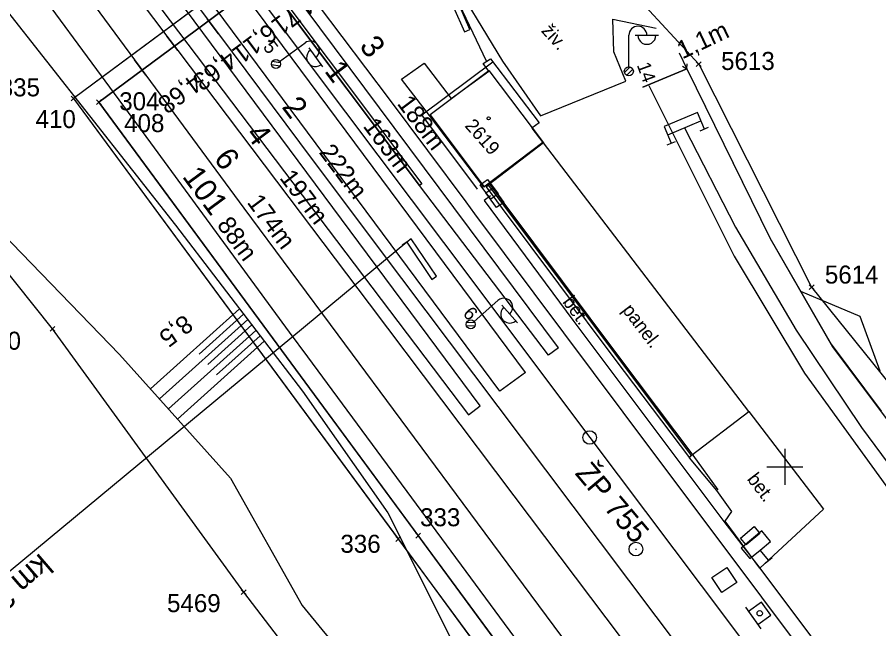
# Model space of a CAD drawing. Extents: x -804166 to -803706, y -1151030 to -1150147.
# Drawn here: x -804085.1 to -803989.6, y -1150318 to -1150250.1 of the extents above; entities that cross this region are included whole.
import ezdxf

# ---------------------------------------------------------------- set-up
doc = ezdxf.new("R2010")
doc.units = 0
for name, color, linetype in [('0381KM032-037P - Vrstva 1', 7, 'Continuous'), ('0381KM032-037P - Vrstva 12', 7, 'Continuous'), ('0381KM032-037P - Vrstva 13', 7, 'Continuous'), ('0381KM032-037P - Vrstva 14', 7, 'Continuous'), ('0381KM032-037P - Vrstva 15', 7, 'Continuous'), ('0381KM032-037P - Vrstva 16', 7, 'Continuous'), ('0381KM032-037P - Vrstva 17', 7, 'Continuous'), ('0381KM032-037P - Vrstva 23', 7, 'Continuous'), ('0381KM032-037P - Vrstva 25', 7, 'Continuous'), ('0381KM032-037P - Vrstva 3', 7, 'Continuous'), ('0381KM032-037P - Vrstva 33', 7, 'Continuous'), ('0381KM032-037P - Vrstva 4', 7, 'Continuous'), ('0381KM032-037P - Vrstva 41', 7, 'Continuous'), ('0381KM032-037P - Vrstva 48', 7, 'Continuous'), ('0381KM032-037P - Vrstva 49', 7, 'Continuous'), ('0381KM032-037P - Vrstva 51', 7, 'Continuous'), ('0381KM032-037P - Vrstva 55', 7, 'Continuous'), ('0381KM032-037P - Vrstva 57', 7, 'Continuous'), ('0381KM032-037P - Vrstva 59', 7, 'Continuous'), ('0381KM032-037P - Vrstva 7', 7, 'Continuous'), ('0381KM032-037P - Vrstva 9', 7, 'Continuous'), ('DZ_CD - CD', 7, 'Continuous'), ('DZ_CD - CD_krizek', 7, 'Continuous'), ('DZ_CD - CD_čísla', 7, 'Continuous'), ('krizky_1000 - Vrstva 1', 7, 'Continuous'), ('szdc - hran DP', 7, 'Continuous'), ('szdc - szdc_cislo', 7, 'Continuous'), ('szdc - szdc_krizek', 7, 'Continuous'), ('VB - VB', 7, 'Continuous'), ('VB - VB_cislo', 7, 'Continuous'), ('VB - VB_krizek', 7, 'Continuous'), ('vyt_sit - stávající', 7, 'Continuous')]:
    doc.layers.add(name, color=color, linetype=linetype)

msp = doc.modelspace()

# ---------------------------------------------------------------- linework, layer by layer
at = {"layer": '0381KM032-037P - Vrstva 1'}
for points in [[(-804087.926, -1150205.285), (-804078.707, -1150215.283), (-804072.371, -1150222.524), (-804072.077, -1150222.855), (-804071.467, -1150223.584), (-804065.479, -1150230.817), (-804059.467, -1150238.509), (-804055.553, -1150243.678), (-804054.356, -1150245.269), (-804043.889, -1150259.222), (-804035.374, -1150270.613), (-804034.4, -1150271.93), (-804017.97, -1150293.92), (-804002.6, -1150314.46), (-803985.38, -1150337.43), (-803955.87, -1150376.72)], [(-804089.349, -1150206.442), (-804078.67, -1150220.695), (-804069.154, -1150233.375), (-804067.857, -1150235.106), (-804059.282, -1150246.533), (-804058.068, -1150248.156), (-804048.703, -1150260.645), (-804037.85, -1150275.13), (-804021.63, -1150296.76), (-804006.14, -1150317.336), (-803988.978, -1150340.287), (-803981.901, -1150349.725)], [(-804090.387, -1150214.375), (-804086.648, -1150219.546), (-804073.823, -1150237.114), (-804072.555, -1150238.826), (-804064.047, -1150250.31), (-804062.807, -1150251.974), (-804052.288, -1150266.049), (-804042.5, -1150279.11), (-804026.546, -1150300.334), (-804011.272, -1150320.629), (-803993.373, -1150344.487), (-803965.171, -1150382.072), (-803953.841, -1150397.189)], [(-804093.97, -1150217.423), (-804088.165, -1150225.674), (-804077.507, -1150240.279), (-804068.519, -1150252.214), (-804067.312, -1150253.815), (-804055.014, -1150270.122), (-804046.09, -1150281.931), (-804030.046, -1150303.209), (-804014.756, -1150323.518), (-803996.92, -1150347.354), (-803968.884, -1150385.416), (-803942.597, -1150419.033)], [(-804095.554, -1150218.377), (-804090.738, -1150227.081), (-804084.011, -1150238.21), (-804078.761, -1150245.777), (-804072.115, -1150254.848), (-804070.853, -1150256.555), (-804059.975, -1150271.287), (-804049.56, -1150285.37), (-804034.127, -1150306.216), (-804018.794, -1150326.862), (-804001.176, -1150350.631), (-803980.37, -1150378.683), (-803972.82, -1150388.417), (-803965.206, -1150397.597)], [(-804088.45, -1150239.448), (-804070.362, -1150264.071), (-804054.977, -1150285.047), (-804052.95, -1150287.79), (-804037.556, -1150308.636), (-804021.871, -1150329.906), (-804004.483, -1150353.558), (-803990.764, -1150372.094)], [(-804011.14, -1150262.39), (-804005.45, -1150273.41), (-803998.73, -1150284.85), (-803991.51, -1150295.63), (-803978.8, -1150312.77), (-803963.69, -1150332.99), (-803952.21, -1150348.36), (-803946.3, -1150356.39), (-803941.6, -1150363.14), (-803936.71, -1150370.83), (-803932.05, -1150378.84), (-803927.78, -1150386.91), (-803924.06, -1150395.18), (-803920.62, -1150403.65), (-803918.06, -1150410.86), (-803915.07, -1150420.32), (-803912.96, -1150427.25), (-803910.49, -1150435.34), (-803907.334, -1150445.05), (-803903.668, -1150454.381), (-803897.938, -1150464.596), (-803891.973, -1150476.598)]]:
    msp.add_lwpolyline(points, dxfattribs=at)
at = {"layer": '0381KM032-037P - Vrstva 12'}
for p, q in [((-804056.315, -1150247.214), (-804040.257, -1150268.603)), ((-804056.555, -1150247.394), (-804040.497, -1150268.783)), ((-804040.257, -1150268.603), (-804040.497, -1150268.783))]:
    msp.add_line(p, q, dxfattribs=at)
at = {"layer": '0381KM032-037P - Vrstva 13'}
for p, q in [((-804011.731, -1150254.056), (-804010.873, -1150255.863)), ((-804032.73, -1150268.635), (-804030.936, -1150271.035)), ((-804030.936, -1150271.035), (-804018.442, -1150287.751)), ((-804018.442, -1150287.751), (-804010.191, -1150298.695)), ((-804010.191, -1150298.695), (-804007.429, -1150302.556))]:
    msp.add_line(p, q, dxfattribs=at)
for points in [[(-804010.873, -1150255.863), (-804015.74, -1150257.89), (-804015.74, -1150257.89), (-804010.873, -1150255.863)], [(-804011.358, -1150255.54), (-804010.873, -1150255.863), (-804010.816, -1150255.283)]]:
    msp.add_lwpolyline(points, dxfattribs=at)
at = {"layer": '0381KM032-037P - Vrstva 14'}
for p, q in [((-804028.769, -1150289.524), (-804076.452, -1150225.306)), ((-804031.587, -1150291.616), (-804079.27, -1150227.397)), ((-804033.774, -1150293.241), (-804081.457, -1150229.022)), ((-804083.366, -1150230.42), (-804035.088, -1150294.233)), ((-804025.083, -1150286.789), (-804026.202, -1150287.61)), ((-804028.769, -1150289.524), (-804031.587, -1150291.616)), ((-804035.088, -1150294.233), (-804033.774, -1150293.241))]:
    msp.add_line(p, q, dxfattribs=at)
for points in [[(-804025.083, -1150286.789), (-804066.443, -1150231.313), (-804073.378, -1150223.272)], [(-804026.202, -1150287.61), (-804040.497, -1150268.783), (-804056.555, -1150247.394), (-804058.991, -1150244.123), (-804066.401, -1150234.117), (-804074.204, -1150223.733)]]:
    msp.add_lwpolyline(points, dxfattribs=at)
at = {"layer": '0381KM032-037P - Vrstva 15'}
for p, q in [((-804012.979, -1150263.176), (-804009.301, -1150261.604)), ((-804009.368, -1150262.72), (-804008.448, -1150262.328)), ((-804013.046, -1150264.292), (-804012.127, -1150263.899))]:
    msp.add_line(p, q, dxfattribs=at)
msp.add_lwpolyline([(-804008.908, -1150262.524), (-804009.694, -1150260.685), (-804013.372, -1150262.256), (-804012.586, -1150264.095)], dxfattribs=at)
at = {"layer": '0381KM032-037P - Vrstva 16'}
for p, q in [((-804026.769, -1150264.064), (-804032.889, -1150268.75)), ((-804003.993, -1150293.855), (-804026.769, -1150264.064)), ((-804033.123, -1150268.934), (-804032.889, -1150268.75)), ((-804018.835, -1150288.051), (-804010.584, -1150298.995)), ((-804018.605, -1150287.794), (-804010.377, -1150298.758)), ((-804010.377, -1150298.758), (-804003.993, -1150293.855)), ((-804010.584, -1150298.995), (-804010.377, -1150298.758))]:
    msp.add_line(p, q, dxfattribs=at)
for points in [[(-804033.123, -1150268.934), (-804031.329, -1150271.335), (-804018.835, -1150288.051)], [(-804032.889, -1150268.75), (-804031.101, -1150271.134), (-804018.605, -1150287.794)], [(-804032.64, -1150269.934), (-804033.342, -1150270.468), (-804023.506, -1150283.74), (-804006.754, -1150306.055), (-804006.626, -1150306.045)], [(-804003.993, -1150293.855), (-803995.701, -1150304.683), (-804002.754, -1150311.23), (-804006.626, -1150306.045), (-804005.862, -1150304.94), (-804007.531, -1150302.641), (-804010.584, -1150298.995)]]:
    msp.add_lwpolyline(points, dxfattribs=at)
at = {"layer": '0381KM032-037P - Vrstva 17'}
msp.add_line((-804033.09, -1150255.012), (-804036.604, -1150247.549), dxfattribs=at)
at = {"layer": '0381KM032-037P - Vrstva 23'}
for points in [[(-804034.075, -1150269.193), (-804040.266, -1150260.959), (-804032.388, -1150255.053)], [(-804039.337, -1150260.913), (-804032.819, -1150256.048), (-804026.769, -1150264.064)], [(-804026.769, -1150264.064), (-804033.291, -1150268.939), (-804039.337, -1150260.913)]]:
    msp.add_lwpolyline(points, dxfattribs=at)
at = {"layer": '0381KM032-037P - Vrstva 25'}
for p, q in [((-804017.295, -1150255.614), (-804017.295, -1150252.114)), ((-804016.595, -1150252.114), (-804013.995, -1150252.114)), ((-804056.033, -1150255.017), (-804053.202, -1150252.96)), ((-804052.79, -1150253.526), (-804051.262, -1150255.63)), ((-804056.932, -1150255.374), (-804055.986, -1150255.524)), ((-804056.837, -1150255.01), (-804055.968, -1150255.148)), ((-804017.773, -1150256.26), (-804017.151, -1150255.638)), ((-804017.534, -1150256.551), (-804016.857, -1150255.874)), ((-804034.447, -1150283.867), (-804031.829, -1150281.544)), ((-804031.364, -1150282.068), (-804029.639, -1150284.013)), ((-804035.307, -1150284.31), (-804034.351, -1150284.367)), ((-804035.247, -1150283.938), (-804034.369, -1150283.991))]:
    msp.add_line(p, q, dxfattribs=at)
for points in [[(-804033.783, -1150268.696), (-804032.976, -1150268.105), (-804031.793, -1150269.718), (-804032.6, -1150270.309), (-804033.783, -1150268.696)], [(-804033.143, -1150269.611), (-804032.329, -1150269.03), (-804031.167, -1150270.657), (-804031.981, -1150271.238), (-804033.143, -1150269.611)], [(-804004.28, -1150308.671), (-804004.923, -1150307.905), (-804003.392, -1150306.619), (-804002.749, -1150307.385), (-804004.28, -1150308.671)]]:
    msp.add_lwpolyline(points, dxfattribs=at)
for centre in [(-804056.438, -1150255.311), (-804056.438, -1150255.311), (-804017.295, -1150256.114), (-804017.295, -1150256.114), (-804034.821, -1150284.199), (-804034.821, -1150284.199)]:
    msp.add_circle(centre, 0.5, dxfattribs=at)
for centre, start, end in [((-804016.295, -1150252.114), 0, 180), ((-804015.295, -1150252.126), 179.29743, 0.70257), ((-804052.614, -1150253.769), 305.99498, 125.99498), ((-804052.036, -1150254.585), 125.29241, 306.69756), ((-804031.165, -1150282.292), 311.5784, 131.5784), ((-804030.511, -1150283.049), 130.87583, 312.28097)]:
    msp.add_arc(centre, 1, start, end, dxfattribs=at)
at = {"layer": '0381KM032-037P - Vrstva 3'}
for p, q in [((-804002.583, -1150315.009), (-804004.023, -1150316.045)), ((-804001.547, -1150316.449), (-804002.583, -1150315.009)), ((-804004.368, -1150315.565), (-804002.642, -1150317.965)), ((-804004.023, -1150316.045), (-804002.987, -1150317.485)), ((-804002.987, -1150317.485), (-804001.547, -1150316.449))]:
    msp.add_line(p, q, dxfattribs=at)
msp.add_circle((-804002.783, -1150316.249), 0.296, dxfattribs=at)
at = {"layer": '0381KM032-037P - Vrstva 33'}
msp.add_lwpolyline([(-804035.533, -1150251.745), (-804034.915, -1150251.471), (-804036.128, -1150248.732), (-804036.747, -1150249.006)], close=True, dxfattribs=at)
at = {"layer": '0381KM032-037P - Vrstva 4'}
for p, q in [((-804062.807, -1150251.974), (-804064.047, -1150250.31)), ((-804067.312, -1150253.815), (-804068.519, -1150252.214)), ((-804070.853, -1150256.555), (-804072.115, -1150254.848))]:
    msp.add_line(p, q, dxfattribs=at)
for points in [[(-804015.087, -1150257.699), (-804005.607, -1150276.645), (-803997.811, -1150289.613), (-803985.988, -1150305.967), (-803963.827, -1150335.545), (-803947.69, -1150357.387), (-803941.599, -1150366.016), (-803933.495, -1150379.543), (-803925.569, -1150395.827), (-803919.567, -1150411.363), (-803915.11, -1150425.701)], [(-804033.342, -1150270.468), (-804023.506, -1150283.74), (-804006.754, -1150306.055), (-804002.754, -1150311.23), (-803984.52, -1150335.594), (-803962.042, -1150365.446)]]:
    msp.add_lwpolyline(points, dxfattribs=at)
at = {"layer": '0381KM032-037P - Vrstva 41'}
msp.add_lwpolyline([(-804006.413, -1150311.159), (-804005.302, -1150312.822), (-804006.965, -1150313.933), (-804008.076, -1150312.27), (-804006.413, -1150311.159)], dxfattribs=at)
at = {"layer": '0381KM032-037P - Vrstva 48'}
for p, q in [((-804060.479, -1150282.472), (-804070.358, -1150291.348)), ((-804060.021, -1150283.069), (-804064.939, -1150287.487)), ((-804059.564, -1150283.666), (-804069.355, -1150292.464)), ((-804059.106, -1150284.263), (-804063.98, -1150288.642)), ((-804058.648, -1150284.86), (-804068.353, -1150293.58)), ((-804058.191, -1150285.457), (-804063.021, -1150289.797)), ((-804057.733, -1150286.054), (-804067.35, -1150294.696))]:
    msp.add_line(p, q, dxfattribs=at)
at = {"layer": '0381KM032-037P - Vrstva 49'}
for points in [[(-804102.718, -1150221.962), (-804093.913, -1150234.53), (-804086.64, -1150248.912), (-804067.583, -1150273.204)], [(-804119.6, -1150227.37), (-804114.18, -1150233.24), (-804110.61, -1150241.24), (-804107.35, -1150246.09), (-804099.61, -1150256.67), (-804091.21, -1150269.57), (-804073.78, -1150287.54), (-804061.47, -1150301.24), (-804053.54, -1150315.4), (-804051.02, -1150318.44), (-804043.408, -1150327.559), (-804036.336, -1150339.315), (-804033.467, -1150348.914), (-804032.832, -1150355.717)], [(-804010.873, -1150255.863), (-804001.608, -1150274.672), (-803994.699, -1150286.679), (-803981.461, -1150304.357), (-803936.046, -1150366.093), (-803921.768, -1150392.538), (-803912.222, -1150419.282), (-803908.812, -1150430.908)], [(-804010.873, -1150255.863), (-804010.873, -1150255.863), (-804001.645, -1150274.597), (-803994.857, -1150286.394), (-803989.305, -1150293.808), (-803989.412, -1150293.739)], [(-804067.583, -1150273.204), (-804053.47, -1150291.615), (-804044.041, -1150305.104), (-804036.583, -1150319.919), (-804030.406, -1150335.369), (-804026.23, -1150342.569), (-804022.745, -1150350.536)], [(-803998.251, -1150280.496), (-803991.69, -1150283.272), (-803989.471, -1150289.341)]]:
    msp.add_lwpolyline(points, dxfattribs=at)
at = {"layer": '0381KM032-037P - Vrstva 51'}
msp.add_line((-804002.162, -1150310.705), (-804001.392, -1150310.067), dxfattribs=at)
for points in [[(-804037.56, -1150244.693), (-804031.308, -1150254.993), (-804027.096, -1150261.05), (-804017.619, -1150257.212), (-804018.951, -1150253.972), (-804019.077, -1150250.328), (-804014.248, -1150251.346)], [(-804015.087, -1150257.699), (-804005.607, -1150276.645), (-803997.811, -1150289.613), (-803985.988, -1150305.967), (-803963.827, -1150335.545), (-803947.69, -1150357.387), (-803941.599, -1150366.016), (-803933.495, -1150379.543), (-803925.569, -1150395.827), (-803919.567, -1150411.363), (-803915.11, -1150425.701)], [(-804001.777, -1150310.386), (-804002.733, -1150309.23), (-804001.577, -1150308.274), (-804002.534, -1150307.118), (-804004.845, -1150309.031), (-804003.889, -1150310.186), (-804002.733, -1150309.23)]]:
    msp.add_lwpolyline(points, dxfattribs=at)
at = {"layer": '0381KM032-037P - Vrstva 55'}
msp.add_lwpolyline([(-804042.49, -1150256.99), (-804040.01, -1150255.2), (-804037.01, -1150259.13), (-804032.83, -1150256.09), (-804033.46, -1150255.26), (-804032.63, -1150254.75), (-804027.25, -1150261.82), (-804028.04, -1150262.42), (-804026.84, -1150264.01), (-804033.36, -1150268.97), (-804039.39, -1150261.01)], close=True, dxfattribs=at)
at = {"layer": '0381KM032-037P - Vrstva 59'}
msp.add_circle((-804032.847, -1150261.342), 0.175, dxfattribs=at)
at = {"layer": '0381KM032-037P - Vrstva 7'}
msp.add_circle((-804021.637, -1150296.751), 0.75, dxfattribs=at)
at = {"layer": '0381KM032-037P - Vrstva 9'}
for p, q in [((-804041.432, -1150274.723), (-804041.93, -1150275.059)), ((-804038.632, -1150278.865), (-804041.432, -1150274.723)), ((-804041.912, -1150275.082), (-804093.564, -1150317.869)), ((-804041.93, -1150275.059), (-804042.427, -1150275.395)), ((-804041.93, -1150275.059), (-804039.129, -1150279.201)), ((-804039.129, -1150279.201), (-804038.632, -1150278.865))]:
    msp.add_line(p, q, dxfattribs=at)
at = {"layer": 'DZ_CD - CD'}
for p, q in [((-804052.699, -1150239.702), (-804078.871, -1150259.126)), ((-804049.901, -1150240.116), (-804076.079, -1150259.544)), ((-804076.079, -1150259.544), (-804049.901, -1150240.116)), ((-804078.871, -1150259.126), (-804042.879, -1150308.001)), ((-804040.665, -1150307.634), (-804076.079, -1150259.544)), ((-804042.879, -1150308.001), (-804006.886, -1150356.876)), ((-804005.251, -1150355.724), (-804040.665, -1150307.634))]:
    msp.add_line(p, q, dxfattribs=at)
at = {"layer": 'DZ_CD - CD_krizek'}
for p, q in [((-804078.606, -1150259.391), (-804079.137, -1150258.861)), ((-804079.137, -1150259.391), (-804078.606, -1150258.861)), ((-804075.814, -1150259.809), (-804076.345, -1150259.279)), ((-804076.345, -1150259.809), (-804075.814, -1150259.279)), ((-804040.4, -1150307.899), (-804040.931, -1150307.369)), ((-804040.931, -1150307.899), (-804040.4, -1150307.369)), ((-804042.614, -1150308.266), (-804043.145, -1150307.736)), ((-804043.145, -1150308.266), (-804042.614, -1150307.736))]:
    msp.add_line(p, q, dxfattribs=at)
at = {"layer": 'krizky_1000 - Vrstva 1'}
for points in [[(-804000, -1150298), (-804000, -1150302)], [(-804002, -1150300), (-803998, -1150300)]]:
    msp.add_lwpolyline(points, dxfattribs=at)
at = {"layer": 'szdc - hran DP'}
for p, q in [((-804081.21, -1150284.7), (-804121.35, -1150234.4)), ((-804017.32, -1150246.9), (-804009.55, -1150255.32)), ((-804009.55, -1150255.32), (-803997.02, -1150280.06)), ((-803997.02, -1150280.06), (-803982.8, -1150297.76)), ((-804060.01, -1150313.9), (-804081.21, -1150284.7)), ((-804033.86, -1150347.88), (-804060.01, -1150313.9))]:
    msp.add_line(p, q, dxfattribs=at)
at = {"layer": 'szdc - szdc_krizek'}
for p, q in [((-804009.285, -1150255.585), (-804009.816, -1150255.055)), ((-804009.816, -1150255.585), (-804009.285, -1150255.055)), ((-803996.755, -1150280.325), (-803997.286, -1150279.795)), ((-803997.286, -1150280.325), (-803996.755, -1150279.795)), ((-804080.945, -1150284.965), (-804081.476, -1150284.435)), ((-804081.476, -1150284.965), (-804080.945, -1150284.435)), ((-804059.745, -1150314.165), (-804060.276, -1150313.635)), ((-804060.276, -1150314.165), (-804059.745, -1150313.635))]:
    msp.add_line(p, q, dxfattribs=at)
at = {"layer": 'VB - VB'}
for p, q in [((-804078.871, -1150259.126), (-804006.886, -1150356.876)), ((-804076.079, -1150259.544), (-804005.251, -1150355.724))]:
    msp.add_line(p, q, dxfattribs=at)
for points in [[(-804051.788, -1150237.573), (-804053.386, -1150238.776), (-804052.699, -1150239.702), (-804078.871, -1150259.126)], [(-804051.788, -1150237.573), (-804049.901, -1150240.116), (-804076.079, -1150259.544)]]:
    msp.add_lwpolyline(points, dxfattribs=at)
at = {"layer": 'VB - VB_krizek'}
for p, q in [((-804078.606, -1150259.391), (-804079.137, -1150258.861)), ((-804079.137, -1150259.391), (-804078.606, -1150258.861)), ((-804075.814, -1150259.809), (-804076.345, -1150259.279)), ((-804076.345, -1150259.809), (-804075.814, -1150259.279))]:
    msp.add_line(p, q, dxfattribs=at)
at = {"layer": 'vyt_sit - stávající'}
msp.add_line((-804016.563, -1150309.123), (-804016.463, -1150309.123), dxfattribs=at)
msp.add_circle((-804016.513, -1150309.123), 0.756, dxfattribs=at)

# ---------------------------------------------------------------- texts
at = {"layer": '0381KM032-037P - Vrstva 1'}
for s, height, rotation, p in [('4,71', 2, 216.86476, (-804052.935, -1150247.536)), ('6,11', 2, 216.77273, (-804057.273, -1150250.69)), ('3', 2.5, 306.87581, (-804047.255, -1150253.344)), ('4,63', 2, 217.02194, (-804061.705, -1150253.696)), ('1', 2.5, 306.86476, (-804051.127, -1150256.098)), ('4,68', 2, 216.44189, (-804065.54, -1150256.267)), ('2', 2.5, 306.77273, (-804055.85, -1150260.088)), ('188m', 2, 306.87581, (-804043.067, -1150259.71)), ('163m', 2, 306.86476, (-804046.844, -1150262.218)), ('4', 2.5, 307.07815, (-804059.864, -1150263.117)), ('222m', 2, 306.77273, (-804051.729, -1150265.12)), ('6', 2.5, 306.48456, (-804063.404, -1150265.803)), ('101', 2.5, 306.4445, (-804066.893, -1150267.81)), ('197m', 2, 307.07815, (-804056.105, -1150267.957)), ('174m', 2, 306.48456, (-804059.714, -1150270.667)), ('88m', 2, 306.4445, (-804063.053, -1150273.176))]:
    msp.add_text(s, height=height, rotation=rotation, dxfattribs=at).set_placement(p)
at = {"layer": '0381KM032-037P - Vrstva 13'}
msp.add_text('1,1m', height=2, rotation=25.38997, dxfattribs=at).set_placement((-804011.359, -1150254.809))
at = {"layer": '0381KM032-037P - Vrstva 16'}
for s, rotation, p in [('bet.', 306.54248, (-804024.711, -1150281.717)), ('panel.', 307.39886, (-804018.102, -1150282.624)), ('bet.', 307.44462, (-804004.253, -1150301.379))]:
    msp.add_text(s, height=1.5, rotation=rotation, dxfattribs=at).set_placement(p)
at = {"layer": '0381KM032-037P - Vrstva 25'}
for s, rotation, p in [('5', 305.99498, (-804057.933, -1150253.429)), ('14', 290, (-804016.427, -1150255.417)), ('6', 311.5784, (-804035.781, -1150283.055))]:
    msp.add_text(s, height=1.5, rotation=rotation, dxfattribs=at).set_placement(p)
at = {"layer": '0381KM032-037P - Vrstva 48'}
msp.add_text('8,5', height=2, rotation=217.47206, dxfattribs=at).set_placement((-804066.628, -1150283.019))
at = {"layer": '0381KM032-037P - Vrstva 51'}
msp.add_text('živ.', height=1.5, rotation=312.04699, dxfattribs=at).set_placement((-804027.078, -1150251.675))
at = {"layer": '0381KM032-037P - Vrstva 57'}
msp.add_text('2619', height=1.5, rotation=311.6073, dxfattribs=at).set_placement((-804035.562, -1150262.21))
at = {"layer": '0381KM032-037P - Vrstva 9'}
msp.add_text('km 32,471', height=2.5, rotation=220.76068, dxfattribs=at).set_placement((-804082.585, -1150309.495))
at = {"layer": 'DZ_CD - CD_čísla'}
for s, p in [('335', (-804087.064, -1150258.899)), ('304', (-804073.811, -1150260.444)), ('333', (-804040.448, -1150306.593)), ('336', (-804049.283, -1150309.537))]:
    msp.add_text(s, height=2, dxfattribs=at).set_placement(p)
at = {"layer": 'szdc - szdc_cislo'}
for s, p in [('5613', (-804007.062, -1150255.971)), ('5614', (-803995.553, -1150279.668)), ('5470', (-804090.658, -1150287.007)), ('5469', (-804068.509, -1150316.12))]:
    msp.add_text(s, height=2, dxfattribs=at).set_placement(p)
at = {"layer": 'VB - VB_cislo'}
for s, p in [('410', (-804083.087, -1150262.416)), ('408', (-804073.264, -1150262.863))]:
    msp.add_text(s, height=2, dxfattribs=at).set_placement(p)
at = {"layer": 'vyt_sit - stávající'}
msp.add_text('ŽP 755', height=2.4, rotation=310, dxfattribs=at).set_placement((-804023.35, -1150300.751))

doc.saveas('drawing.dxf')
